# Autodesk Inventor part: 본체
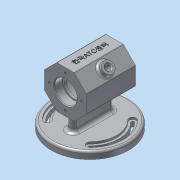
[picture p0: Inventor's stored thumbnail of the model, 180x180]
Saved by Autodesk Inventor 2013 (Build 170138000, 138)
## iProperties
Created: 2017-06
Part Number: 본체
Material: 알루미늄 6061
Document SubType Name: Modeling
Designer: narae
Density: 1 g/cm^3
Author: narae
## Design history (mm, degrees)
sketch "스케치1" dims "d0" = 60
  geometry: L1 (12.426, 30)-(30, 12.426); L2 (30, 12.426)-(30, -12.426); L3 (30, -12.426)-(12.426, -30); L4 (12.426, -30)-(-12.426, -30); L5 (-12.426, -30)-(-30, -12.426); L6 (-30, -12.426)-(-30, 12.426); L7 (-30, 12.426)-(-12.426, 30); L8 (-12.426, 30)-(12.426, 30); 6 further points
  constraints: 16 end point, 3 coincident, 2 midpoint, 1 horizontal alignment, 1 vertical alignment, 19 other
extrude "돌출1" new body sketch "스케치1" stored distance "d1" = 70; taper "d2" = 0 deg
sketch "스케치3"
  geometry: C1 r 16 at (0, 0); 1 further point
  constraints: 1 centre point, 1 coincident
  dimensions: "d5" = 32 diameter of C1
extrude "돌출2" cut sketch "스케치3" distance "d6" = 12; taper "d7" = 0 deg
sketch "스케치4"
  geometry: C1 r 16 at (0, 0) reference; C2 r 14 at (0, 0)
  constraints: 1 centre point, 1 coincident
  dimensions: "d8" = 28 diameter of C2
extrude "돌출3" cut sketch "스케치4" distance "d9" = 3; taper "d10" = 0 deg
sketch "스케치5"
  geometry: C1 r 14 at (0, 0) reference; C2 r 25 at (0, 0)
  constraints: 1 centre point, 1 coincident
  dimensions: "d11" = 50 diameter of C2
extrude "돌출4" cut sketch "스케치5" distance "d12" = 40; taper "d13" = 0 deg
fillet "모깎기1" dims "d14" = 3
fillet "모깎기2" dims "d15" = 0.3
chamfer "모따기1" distance "d16" = 1; stored, may be unused: second distance "d17" = 2, angle "d18" = 45 deg
node "작업 평면1"
sketch "스케치7"
  geometry: C1 r 55 at (0, 0); 1 further point
  constraints: 1 centre point, 1 coincident
  dimensions: "d31" = 110 diameter of C1
extrude "돌출5" join sketch "스케치7" distance "d32" = 10; taper "d33" = 0 deg
sketch "스케치8"
  geometry: L1 (0, 0)-(-43, 0); L2 (0, 0)-(-30.406, -30.406); L3 (0, 0)-(-30.406, 30.406); C1 r 55 at (0, 0) reference; A1 r 5 centre (-30.406, -30.406) between (-26.87, -26.87) and (-33.941, -33.941); A2 r 5 centre (-30.406, 30.406) between (-26.87, 26.87) and (-33.941, 33.941); A3 r 38 centre (0, 0) between (-26.87, 26.87) and (-26.87, -26.87); A4 r 48 centre (0, 0) between (-33.941, 33.941) and (-33.941, -33.941)
  constraints: 8 point on circle, 6 end point, 4 centre point, 4 coincident, 2 tangent, 1 horizontal, 1 perpendicular
  dimensions: "d34" = 43 distance of L1.start L1.end; "d36" = 43 distance of L1.start L2.end; "d37" = 45 deg angle of L2 L1; "d38" = 10 diameter of A1; "d39" = 43 distance of L1.start L3.end; "d40" = 10 diameter of A2
extrude "돌출6" cut sketch "스케치8" distance "d41" = 3; taper "d42" = 0 deg
sketch "스케치9"
  geometry: A1 r 5 centre (-30.406, 30.406) between (-26.87, 26.87) and (-33.941, 33.941) reference; A2 r 5 centre (-30.406, -30.406) between (-33.941, -33.941) and (-26.87, -26.87) reference; A3 r 38 centre (0, 0) between (-26.87, 26.87) and (-26.87, -26.87) reference; A4 r 2 centre (-30.406, -30.406) between (-31.82, -31.82) and (-28.991, -28.991); A5 r 2 centre (-30.406, 30.406) between (-31.82, 31.82) and (-28.991, 28.991); A6 r 41 centre (0, 0) between (-28.991, 28.991) and (-28.991, -28.991); A7 r 45 centre (0, 0) between (-31.82, 31.82) and (-31.82, -31.82)
  constraints: 8 point on circle, 4 centre point, 4 coincident, 2 tangent
  dimensions: "d46" = 4 diameter of A4; "d47" = 4 diameter of A5
extrude "돌출7" cut sketch "스케치9" distance "d48" = 7; taper "d49" = 0 deg
sketch "스케치10"
  geometry: L1 (5, -24)-(-5, -24); L2 (-5, -24)-(-5, 24); L3 (-5, 24)-(5, 24); L4 (5, 24)-(5, -24); L5 (5, -24)-(-5, 24); L6 (-5, -24)-(5, 24); C1 r 55 at (0, 0) reference; 2 further points
  constraints: 12 end point, 4 midpoint, 2 horizontal alignment, 2 parallel, 1 horizontal, 1 perpendicular, 4 other
  dimensions: "d53" = 10 distance of L2.end L3.end; "d54" = 48 distance of L1.end L2.end
extrude "돌출8" join sketch "스케치10" stored distance "d55" = 7; taper "d56" = 0 deg
fillet "모깎기3" dims "d57" = 5
sketch "스케치15"
  geometry: L1 (0, 0)-(0, 37); L2 (0, 0)-(26.163, 26.163); 1 further point
  constraints: 4 end point, 1 coincident, 1 vertical
  dimensions: "d73" = 37 distance of L1.start L1.end; "d74" = 37 distance of L1.start L2.end; "d75" = 45 deg angle of L2 L1
node "작업 평면3"
sketch "스케치16"
  geometry: C1 r 8 at (0, 0); 1 further point
  constraints: 1 centre point, 1 coincident
  dimensions: "d76" = 16 diameter of C1
extrude "돌출11" join sketch "스케치16" stored distance "d77" = 7; taper "d78" = 0 deg
sketch "스케치17"
  geometry: C1 r 8 at (0, 0) reference; C2 r 4 at (0, 0)
  constraints: 1 centre point, 1 coincident
  dimensions: "d79" = 8 diameter of C2
extrude "돌출12" cut sketch "스케치17" stored distance "d80" = 7; taper "d81" = 0 deg
chamfer "모따기3" distance "d82" = 1; stored, may be unused: second distance "d83" = 2, angle "d84" = 45 deg
fillet "모깎기4" dims "d85" = 1
sketch "스케치18"
  geometry: L1 (12.012, 30)-(-12.012, 30) reference; L2 (0, 0)-(0, 23); C1 r 17 at (0, 0) reference; 1 further point
  constraints: 2 end point, 1 coincident, 1 perpendicular
  dimensions: "d86" = 23 distance of L2.start L2.end
hole "구멍2" sketch "스케치18" at (0, 23) diameter "d87" = 3.242; stored, may be unused: countersink angle "d91" = 90 deg, drill point angle "d93" = 118 deg; dims "d88" = 8, "d89" = 4, "d90" = 2, "d92" = 10
fillet "모깎기5" dims "d97" = 5
fillet "모깎기6" dims "d98" = 3
sketch "스케치19"
  geometry: L1 (24.024, 0)-(0, 0) reference; L2 (-17.988, 70)-(-17.988, 0) reference; 2 further points
  constraints: 1 other
  dimensions: "d99" = 35 distance from line of point (12.012, 35) L1; "d100" = 30 distance from line of point (12.012, 35) L2
feature "엠보싱1" sketch "스케치19" dims "d0" = 60, "d101" = 0.5, "d102" = 0
fillet "모깎기7" dims "d103" = 3
node "솔리드1"
mirror "대칭1"
mirror "대칭2"
pattern_circular "원형 패턴2" dims angle "d44" = 360 deg
pattern_circular "원형 패턴3" dims angle "d51" = 360 deg
pattern_circular "원형 패턴4" dims angle "d95" = 360 deg
mirror "대칭4"
other parameters: "d30" = -62
